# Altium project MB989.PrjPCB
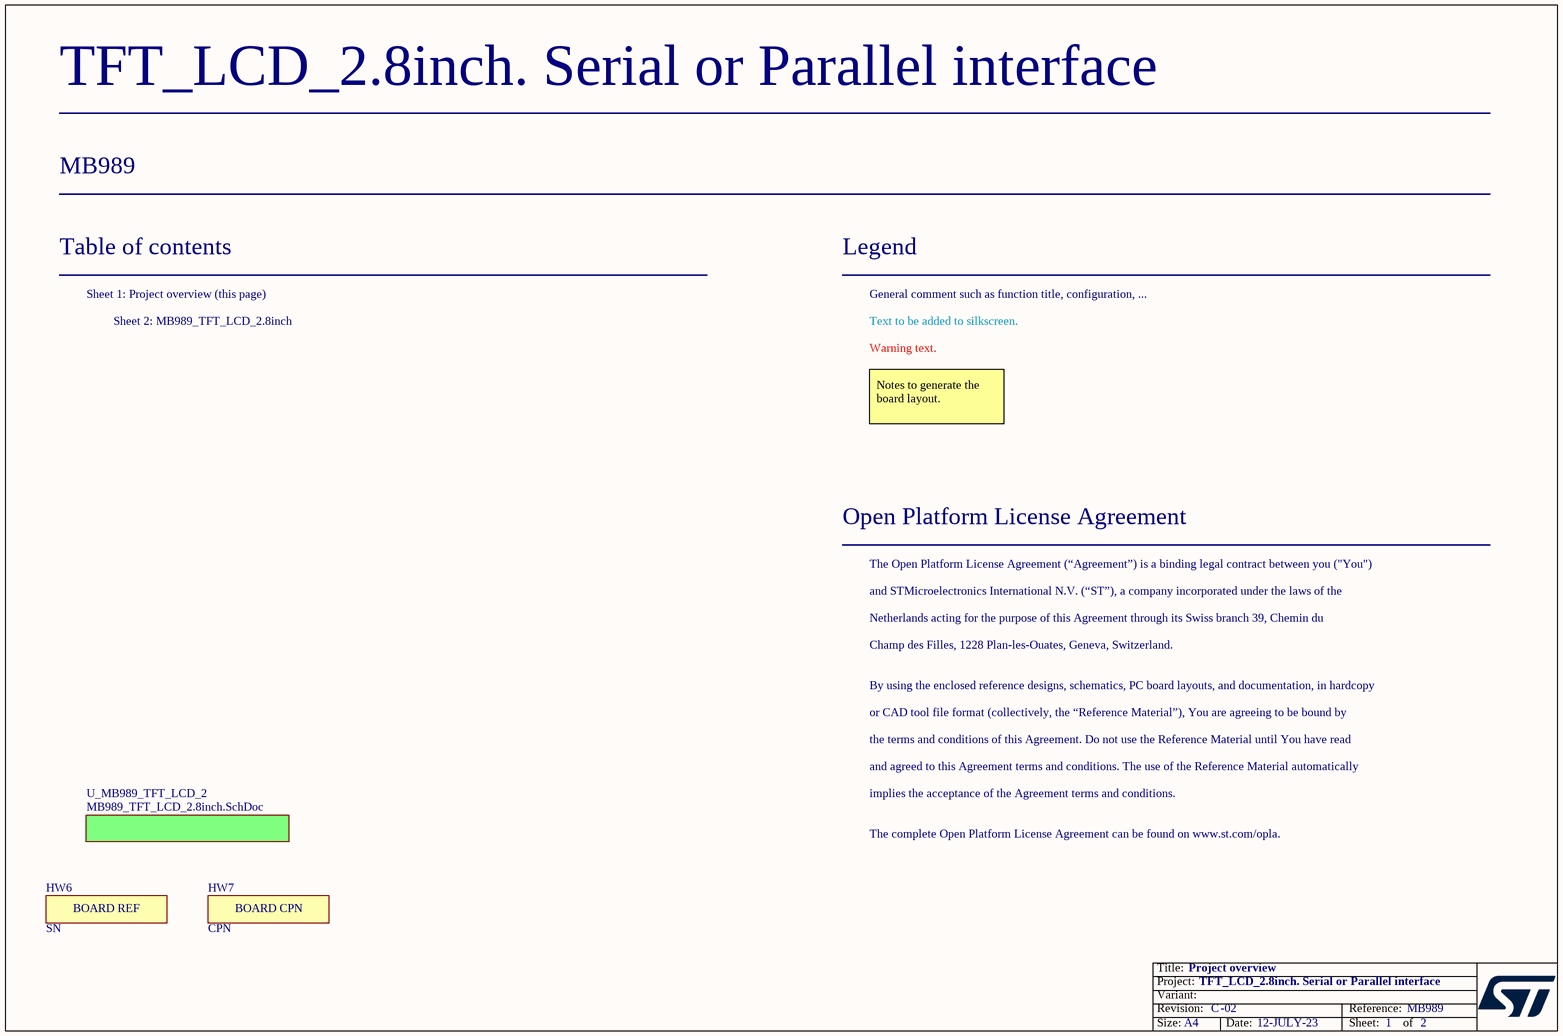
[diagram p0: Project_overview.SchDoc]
Board_Reference: MB989; Board_PCB_Revision: C; Board_Name: TFT_LCD_2.8inch. Serial or Parallel interface; Board_Document_Date: 12-JULY-23; Board_Assembly_Revision: 02
2 sheets, 64 parts. Net scope: global (net labels, ports and power ports of the same name join across sheets).
Board file: MB989.PcbDoc
Sheets:
  Project_overview.SchDoc
    U_MB989_TFT_LCD_2 = MB989_TFT_LCD_2.8inch.SchDoc

## Sheet Project_overview.SchDoc: Project overview
size A4; Date: Not used; ApprovedBy: Not used; CheckedBy: Not used; Author: Not used; CompanyName: STMicroelectronics; DrawnBy: Not used; Engineer: Not used; Organization: Not used; Address1: Not used; Address2: Not used; Address3: Not used; Address4: Not used; DocumentNumber: 1; Revision: Not used; SheetNumber: 1; SheetTotal: 2

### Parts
HW6  value SN  [STICKER_25X9]  (hidden comment: STICKER_BOARD_REF)  (no BOM)
HW7  value CPN  [STICKER_25X9]  (hidden comment: STICKER_BOARD_CPN)  (no BOM)

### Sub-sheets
U_MB989_TFT_LCD_2 = MB989_TFT_LCD_2.8inch.SchDoc: no entries

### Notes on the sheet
- Table of contents
- Sheet 1: Project overview (this page)
- Legend
- General comment such as function title, configuration, ...
- Sheet 2: MB989_TFT_LCD_2.8inch
- Text to be added to silkscreen.
- Warning text.
- Notes to generate the board layout.
- Open Platform License Agreement
- The Open Platform License Agreement (“Agreement”) is a binding legal contract between you ("You")
- and STMicroelectronics International N.V. (“ST”), a company incorporated under the laws of the
- Netherlands acting for the purpose of this Agreement through its Swiss branch 39, Chemin du
- Champ des Filles, 1228 Plan-les-Ouates, Geneva, Switzerland.
- By using the enclosed reference designs, schematics, PC board layouts, and documentation, in hardcopy
- or CAD tool file format (collectively, the “Reference Material”), You are agreeing to be bound by
- the terms and conditions of this Agreement. Do not use the Reference Material until You have read
- and agreed to this Agreement terms and conditions. The use of the Reference Material automatically
- implies the acceptance of the Agreement terms and conditions.
- The complete Open Platform License Agreement can be found on www.st.com/opla.

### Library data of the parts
HW6 = MCD-00235: Sticker to mention board reference + serial number; Part_Type: Mechanical; Provided_By: SUBCO
HW7 = MCD-00547: Sticker to mention board CPN code; Part_Type: Mechanical; Provided_By: SUBCO

## Sheet MB989_TFT_LCD_2.8inch.SchDoc: LCD
size A4; Date: Not used; ApprovedBy: Not used; CheckedBy: Not used; Author: Not used; CompanyName: STMicroelectronics; DrawnBy: Not used; Engineer: Not used; Organization: Not used; Address1: Not used; Address2: Not used; Address3: Not used; Address4: Not used; DocumentNumber: 2; Revision: Not used; SheetNumber: 2; SheetTotal: 2
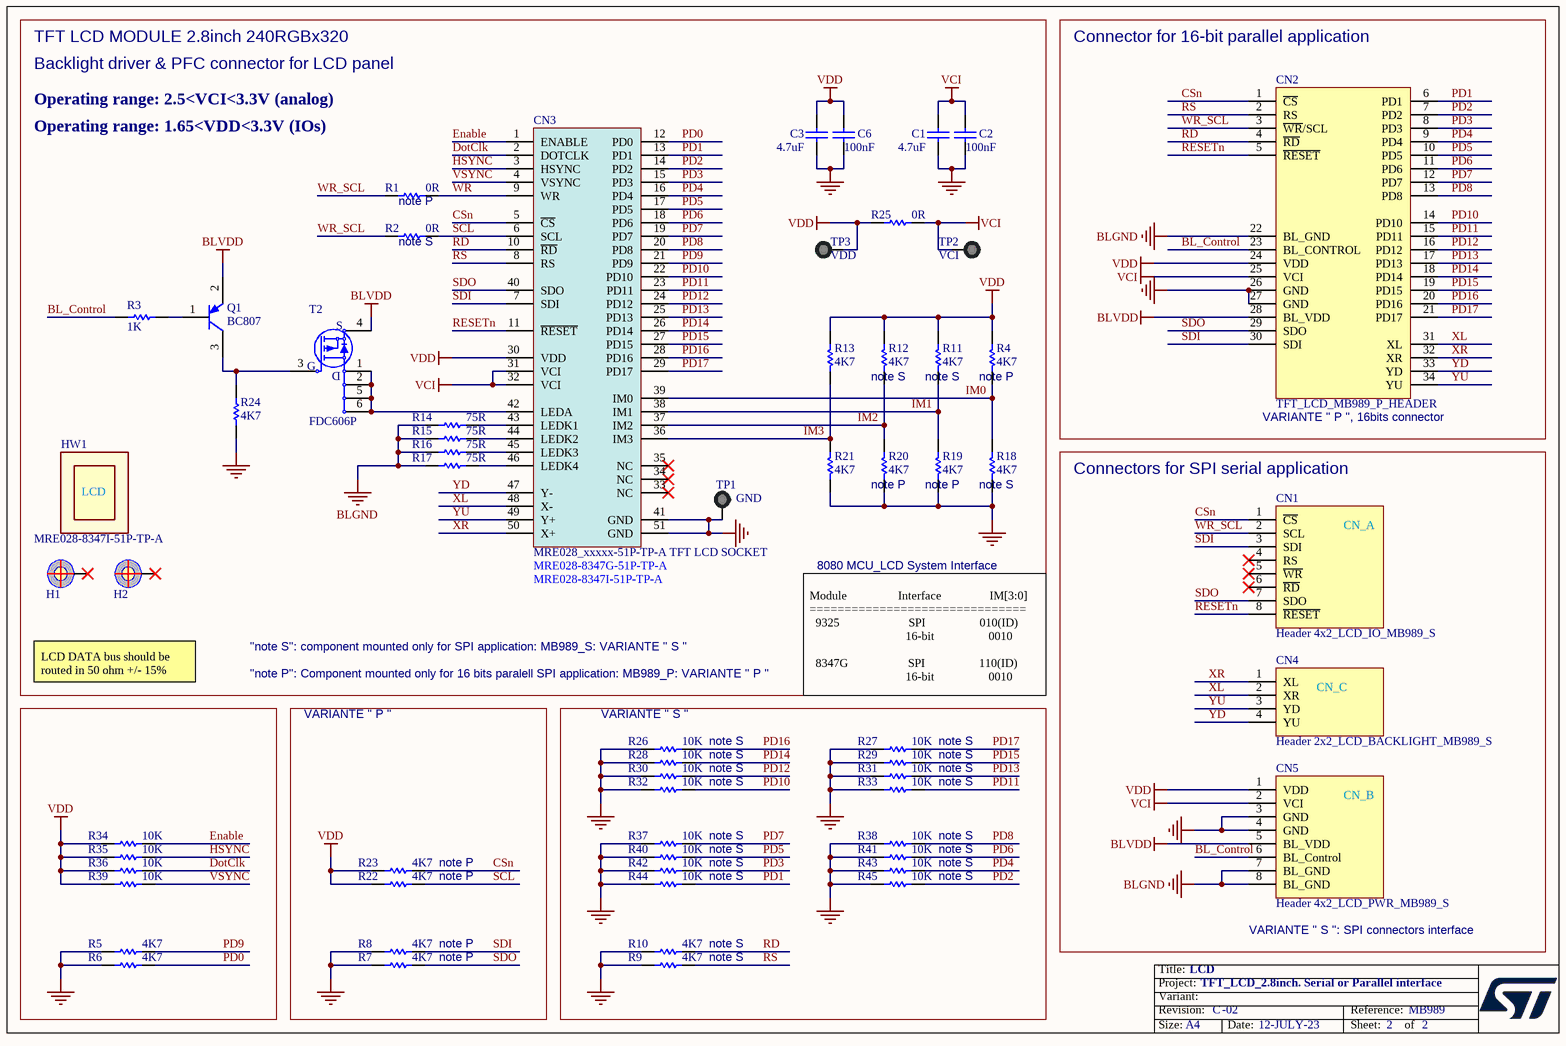
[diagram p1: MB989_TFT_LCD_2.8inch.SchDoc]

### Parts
C1  value 4.7uF  [C0603_H0P8]  (hidden comment: Capacitor)
C2  value 100nF  [C0402]  (hidden comment: Capacitor)
C3  value 4.7uF  [C0603_H0P8]  (hidden comment: Capacitor)
C6  value 100nF  [C0402]  (hidden comment: Capacitor)
CN1  Header 4x2_LCD_IO_MB989_S  [CON_SAMTEC_TSW-104-07-X-D_INV]
CN2  value TFT_LCD_MB989_P_HEADER  [CON_SAMTEC_TSW-117-07-X-D_INV]  (hidden comment: Header 17x2_LCD_TFT_MB989_P)
CN3  value MRE028_xxxxx-51P-TP-A TFT LCD SOCKET  [CON_OMRON_XF2B-5145-31A_INV]  (hidden comment: SOCKET_MRE028_xxxxx-51P-TP-A)
CN4  Header 2x2_LCD_BACKLIGHT_MB989_S  [CON_SAMTEC_TSW-102-07-X-D]
CN5  Header 4x2_LCD_PWR_MB989_S  [CON_SAMTEC_TSW-104-07-X-D_INV]
H1  POSITION HOLE  [NPTH_350]  (value not drawn)  (no BOM)
H2  POSITION HOLE  [NPTH_350]  (value not drawn)  (no BOM)
HW1  value MRE028-8347I-51P-TP-A  [LCD_DRAWING_PROJET-MB989]  (hidden comment: LCD_MODULE)
Q1  value BC807  [ICC_SOT23-3L_H1P12]  (hidden comment: PNP_SOT23)
R1  value 0R  [R0603]  (hidden comment: Resistor)
R2  value 0R  [R0603]  (hidden comment: Resistor)
R3  value 1K  [R0603]  (hidden comment: Resistor)
R4  value 4K7  [R0603]  (hidden comment: Resistor)
R5  value 4K7  [R0603]  (hidden comment: Resistor)
R6  value 4K7  [R0603]  (hidden comment: Resistor)
R7  value 4K7  [R0603]  (hidden comment: Resistor)
R8  value 4K7  [R0603]  (hidden comment: Resistor)
R9  value 4K7  [R0603]  (hidden comment: Resistor)
R10  value 4K7  [R0603]  (hidden comment: Resistor)
R11  value 4K7  [R0603]  (hidden comment: Resistor)
R12  value 4K7  [R0603]  (hidden comment: Resistor)
R13  value 4K7  [R0603]  (hidden comment: Resistor)
R14  value 75R  [R0603]  (hidden comment: Resistor)
R15  value 75R  [R0603]  (hidden comment: Resistor)
R16  value 75R  [R0603]  (hidden comment: Resistor)
R17  value 75R  [R0603]  (hidden comment: Resistor)
R18  value 4K7  [R0603]  (hidden comment: Resistor)
R19  value 4K7  [R0603]  (hidden comment: Resistor)
R20  value 4K7  [R0603]  (hidden comment: Resistor)
R21  value 4K7  [R0603]  (hidden comment: Resistor)
R22  value 4K7  [R0603]  (hidden comment: Resistor)
R23  value 4K7  [R0603]  (hidden comment: Resistor)
R24  value 4K7  [R0603]  (hidden comment: Resistor)
R25  value 0R  [R0603]  (hidden comment: Resistor)
R26  value 10K  [R0402]  (hidden comment: Resistor)
R27  value 10K  [R0402]  (hidden comment: Resistor)
R28  value 10K  [R0402]  (hidden comment: Resistor)
R29  value 10K  [R0402]  (hidden comment: Resistor)
R30  value 10K  [R0402]  (hidden comment: Resistor)
R31  value 10K  [R0402]  (hidden comment: Resistor)
R32  value 10K  [R0402]  (hidden comment: Resistor)
R33  value 10K  [R0402]  (hidden comment: Resistor)
R34  value 10K  [R0402]  (hidden comment: Resistor)
R35  value 10K  [R0402]  (hidden comment: Resistor)
R36  value 10K  [R0402]  (hidden comment: Resistor)
R37  value 10K  [R0402]  (hidden comment: Resistor)
R38  value 10K  [R0402]  (hidden comment: Resistor)
R39  value 10K  [R0402]  (hidden comment: Resistor)
R40  value 10K  [R0402]  (hidden comment: Resistor)
R41  value 10K  [R0402]  (hidden comment: Resistor)
R42  value 10K  [R0402]  (hidden comment: Resistor)
R43  value 10K  [R0402]  (hidden comment: Resistor)
R44  value 10K  [R0402]  (hidden comment: Resistor)
R45  value 10K  [R0402]  (hidden comment: Resistor)
T2  FDC606P  [MOS_SOT23-6L]
TP1  value GND  [TP_PTH_1MM_2MM]  (hidden comment: Test_Point_PTH_1mm_2mm)
TP2  value VCI  [TP_PTH_1MM_2MM]  (hidden comment: Test_Point_PTH_1mm_2mm)
TP3  value VDD  [TP_PTH_1MM_2MM]  (hidden comment: Test_Point_PTH_1mm_2mm)

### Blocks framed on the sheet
Connector for 16-bit parallel application: CN2
Connectors for SPI serial application: CN1 CN4 CN5

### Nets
BLGND: CN2.22(BL_GND) CN5.7(BL_GND) CN5.8(BL_GND) R14.1 R15.1 R16.1 R17.1
BLVDD: CN2.28(BL_VDD) CN5.5(BL_VDD) Q1.2(E) T2.4(S)
GND: C1.1 C2.1 C3.1 C6.1 CN2.26(GND) CN2.27(GND) CN3.41(GND) CN3.51(GND) CN5.3(GND) CN5.4(GND) R5.2 R6.2 R7.2 R8.2 R9.2 R10.2 R18.1 R19.1 R20.1 R21.1 R24.1 R26.1 R27.1 R28.1 R29.1 R30.1 R31.1 R32.1 R33.1 R37.1 R38.1 R40.1 R41.1 R42.1 R43.1 R44.1 R45.1 TP1.1
VCI: C1.2 C2.2 CN2.25(VCI) CN3.31(VCI) CN3.32(VCI) CN5.2(VCI) R25.2 TP2.1
VDD: C3.2 C6.2 CN2.24(VDD) CN3.30(VDD) CN5.1(VDD) R4.2 R11.2 R12.2 R13.2 R22.2 R23.2 R25.1 R34.1 R35.1 R36.1 R39.1 TP3.1
BL_Control: CN2.23(BL_CONTROL) CN5.6(BL_Control) R3.1
CSn: CN1.1(~{CS}) CN2.1(~{CS}) CN3.5(~{CS}) R23.1
DotClk: CN3.2(DOTCLK) R36.2
Enable: CN3.1(ENABLE) R34.2
HSYNC: CN3.3(HSYNC) R35.2
IM0: CN3.39(IM0) R4.1 R18.2
IM1: CN3.38(IM1) R11.1 R19.2
IM2: CN3.37(IM2) R12.1 R20.2
IM3: CN3.36(IM3) R13.1 R21.2
PD0: CN3.12(PD0) R6.1
PD1: CN2.6(PD1) CN3.13(PD1) R44.2
PD2: CN2.7(PD2) CN3.14(PD2) R45.2
PD3: CN2.8(PD3) CN3.15(PD3) R42.2
PD4: CN2.9(PD4) CN3.16(PD4) R43.2
PD5: CN2.10(PD5) CN3.17(PD5) R40.2
PD6: CN2.11(PD6) CN3.18(PD6) R41.2
PD7: CN2.12(PD7) CN3.19(PD7) R37.2
PD8: CN2.13(PD8) CN3.20(PD8) R38.2
PD9: CN3.21(PD9) R5.1
PD10: CN2.14(PD10) CN3.22(PD10) R32.2
PD11: CN2.15(PD11) CN3.23(PD11) R33.2
PD12: CN2.16(PD12) CN3.24(PD12) R30.2
PD13: CN2.17(PD13) CN3.25(PD13) R31.2
PD14: CN2.18(PD14) CN3.26(PD14) R28.2
PD15: CN2.19(PD15) CN3.27(PD15) R29.2
PD16: CN2.20(PD16) CN3.28(PD16) R26.2
PD17: CN2.21(PD17) CN3.29(PD17) R27.2
RD: CN2.4(~{RD}) CN3.10(~{RD}) R10.1
RESETn: CN1.8(~{RESET}) CN2.5(~{RESET}) CN3.11(~{RESET})
RS: CN2.2(RS) CN3.8(RS) R9.1
SCL: CN3.6(SCL) R2.2 R22.1
SDI: CN1.3(SDI) CN2.30(SDI) CN3.7(SDI) R8.1
SDO: CN1.7(SDO) CN2.29(SDO) CN3.40(SDO) R7.1
VSYNC: CN3.4(VSYNC) R39.2
WR: CN3.9(WR) R1.2
WR_SCL: CN1.2(SCL) CN2.3(~{WR}/SCL) R1.1 R2.1
XL: CN2.31(XL) CN3.48(X-) CN4.2(XR)
XR: CN2.32(XR) CN3.50(X+) CN4.1(XL)
YD: CN2.33(YD) CN3.47(Y-) CN4.4(YU)
YU: CN2.34(YU) CN3.49(Y+) CN4.3(YD)
NetCN3_42: CN3.42(LEDA) T2.1(S) T2.2(S) T2.5(D) T2.6(D)
NetCN3_43: CN3.43(LEDK1) R14.2
NetCN3_44: CN3.44(LEDK2) R15.2
NetCN3_45: CN3.45(LEDK3) R16.2
NetCN3_46: CN3.46(LEDK4) R17.2
NetQ1_1: Q1.1(B) R3.2
NetQ1_3: Q1.3(C) R24.2 T2.3(G)

Not connected (* = marked no-connect by the designer): CN1 4(RS)* 5(~{WR})* 6(~{RD})*; CN3 33(NC)* 34(NC)* 35(NC)*; H1 1*; H2 1*

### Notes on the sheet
- TFT LCD MODULE 2.8inch 240RGBx320
- Operating range: 2.5<VCI<3.3V (analog)
- Backlight driver & PFC connector for LCD panel
- Operating range: 1.65<VDD<3.3V (IOs)
- (near R2) note S
- (near R1) note P
- (near R13) note S
- (near R12) note S
- (near R11) note P
- (near CN2) VARIANTE " P ", 16bits connector
- (near R21) note P
- (near R20) note P
- (near R19) note S
- (near CN3) MRE028-8347G-51P-TP-A
- (near CN3) MRE028-8347I-51P-TP-A
- 8080 MCU_LCD System Interface
- "note S": component mounted only for SPI application: MB989_S: VARIANTE " S "
- LCD DATA bus should be routed in 50 ohm +/- 15%
- "note P": Component mounted only for 16 bits paralell SPI application: MB989_P: VARIANTE " P "
- VARIANTE " P "
- VARIANTE " S "
- Module                 Interface                IM[3:0]
  ===============================
  9325                       SPI                  010(ID)
  16-bit                  0010
  8347G                    SPI                  110(ID)
  16-bit                  0010
- note S
- note P
- (near CN5) VARIANTE " S ": SPI connectors interface

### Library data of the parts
C1 C3 = MCD-03342: Capacitor, MLCC, 4.7uF, 10V, X5R, +/-20%, 0603, T=0.8mm; Part_Preference: Recommended; Manufacturer: YAGEO; Manufacturer_Part_Number: CC0603MRX5R6BB475; Component_Country_Of_Origin: China, Taiwan; ShowFields: YES; ID: 5458
C2 C6 = MCD-00006: Capacitor, MLCC, 100nF, 16V, X7R, 10%, 0402, T=0.5mm; Manufacturer_Part_Number: CC0402KRX7R7BB104; Manufacturer: YAGEO; Alternate_Manufacturer_Part_Number: GCM155R71C104KA55D; Alternate_Manufacturer: MURATA; Provided_By: SUBCO
CN1 = MCD-01658: Header, 4x1, 2,54mm, VR, TH, Height 5.84mm/2.54mm, for TFT LCD MODULE MB989_S: pinning inverted; Part_Type: Connector; Manufacturer_Part_Number: TSW-104-07-G-D; Manufacturer: SAMTEC; Provided_By: SUBCO
CN2 = MCD-01343: Header, 17x2, 2,54mm, VR, TH, Height 5.84mm/2.54mm for TFT_LCD MB989_P; Part_Type: Connector; Manufacturer_Part_Number: TSW-117-07-G-D; Manufacturer: SAMTEC; Provided_By: SUBCO
CN3 = MCD-01657: FCP connector for MRE028_xxxxx-51P-TP-A TFT LCD 2.8inch 320x240; Manufacturer_Part_Number: XF2B-5145-31A; Manufacturer: OMRON; Provided_By: SUBCO
CN4 = MCD-01665: Header, 2x2, 2,54mm, VR, TH, Height 5.84mm/2.54mm, for TFT LCD MB989_P: Backlight; Part_Type: Connector; Manufacturer_Part_Number: TSW-102-07-G-D; Manufacturer: SAMTEC; Provided_By: SUBCO
CN5 = MCD-01659: Header, 4x2, 2,54mm, VR, TH, Height 5.84mm/2.54mm for TFT LCD MODULE MB989_S: pinning inverted; Part_Type: Connector; Manufacturer_Part_Number: TSW-104-07-G-D; Manufacturer: SAMTEC; Provided_By: SUBCO
H1 H2 = MCD-01368: POSITION HOLE C3R5D3R5; Part_Type: Mechanical
HW1 = MCD-01419: Display 2.8inch SPI or 16-bit parallel; Manufacturer: SHANGHAI MOORING ELECTRONICS TECHNOLOGY; BMS_Part_Number: 8001057; Provided_By: ST
Q1 = MCD-01527: Transistor Bipolar PNP, 45V, 500mA, 100MHz, 300mW, SOT23-3; Part_Type: IC; Manufacturer: NEXPERIA; Alternate_Manufacturer: NXP; Provided_By: SUBCO
R1 R2 R25 = MCD-00056: Resistor,0R,0603,5%,1/10W; Manufacturer_Part_Number: RC0603JR-070RL; Manufacturer: YAGEO; Provided_By: SUBCO
R3 = MCD-00070: Resistor,1K,0603,1%,1/10W; Manufacturer_Part_Number: RC0603FR-071KL; Manufacturer: YAGEO; Provided_By: SUBCO
R4-R13 R18-R24 = MCD-00219: Resistor,4K7,0603,1%,1/10W; Manufacturer_Part_Number: RC0603FR-074K7L; Manufacturer: YAGEO; Provided_By: SUBCO
R14-R17 = MCD-00516: Resistor,75R,0603,1%,1/10W; Manufacturer_Part_Number: RC0603FR-0775RL; Manufacturer: YAGEO; BMS_Part_Number: 9129726; Provided_By: SUBCO
R26-R45 = MCD-00053: Resistor,10K,0402,1%,1/16W; Manufacturer_Part_Number: RC0402FR-0710KL; Manufacturer: YAGEO; Provided_By: SUBCO
T2 = MCD-01655: MOSFET, P-Channel , Vgs(th): -1.5V, Id: -6A, Vds(max): -12V, Vgs(max): +/-8V, Rdson:26mohm@Vgs=-4.5V; Part_Type: IC; Manufacturer: ON SEMICONDUCTOR; Provided_By: SUBCO
TP1-TP3 = MCD-01506: Test Point trought hole 1mm/2mm; Part_Type: Mechanical

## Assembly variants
P: not fitted CN1 CN4 CN5 R2 R4 R9 R10 R12 R13 R19 R25 R26 R27 R28 R29 R30 R31 R32 R33 R37 R38 R40 R41 R42 R43 R44 R45
S: not fitted CN2 R1 R4 R7 R8 R11 R20 R21 R22 R23 R25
